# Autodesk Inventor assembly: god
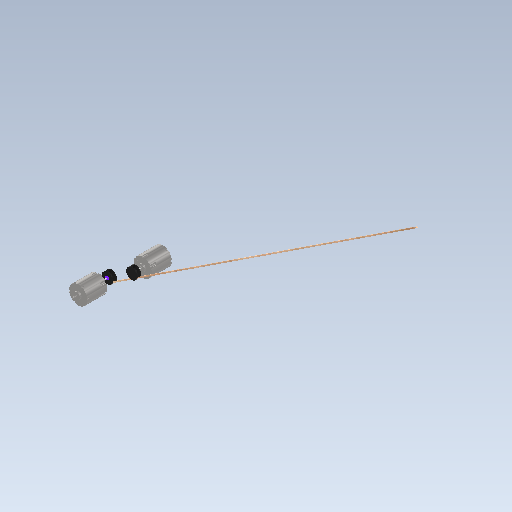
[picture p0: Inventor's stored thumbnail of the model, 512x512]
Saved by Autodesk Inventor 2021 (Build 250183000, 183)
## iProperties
Created: 2021-07
Part Number: god
Document SubType Name: Assembly
Designer: user
Author: user
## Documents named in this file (2)
- C:\Users\user\Downloads\god.iam
- C:\Users\user\Downloads\555.iam
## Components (1 placed, 1 different names)
1. 555:1 [sub-assembly]
